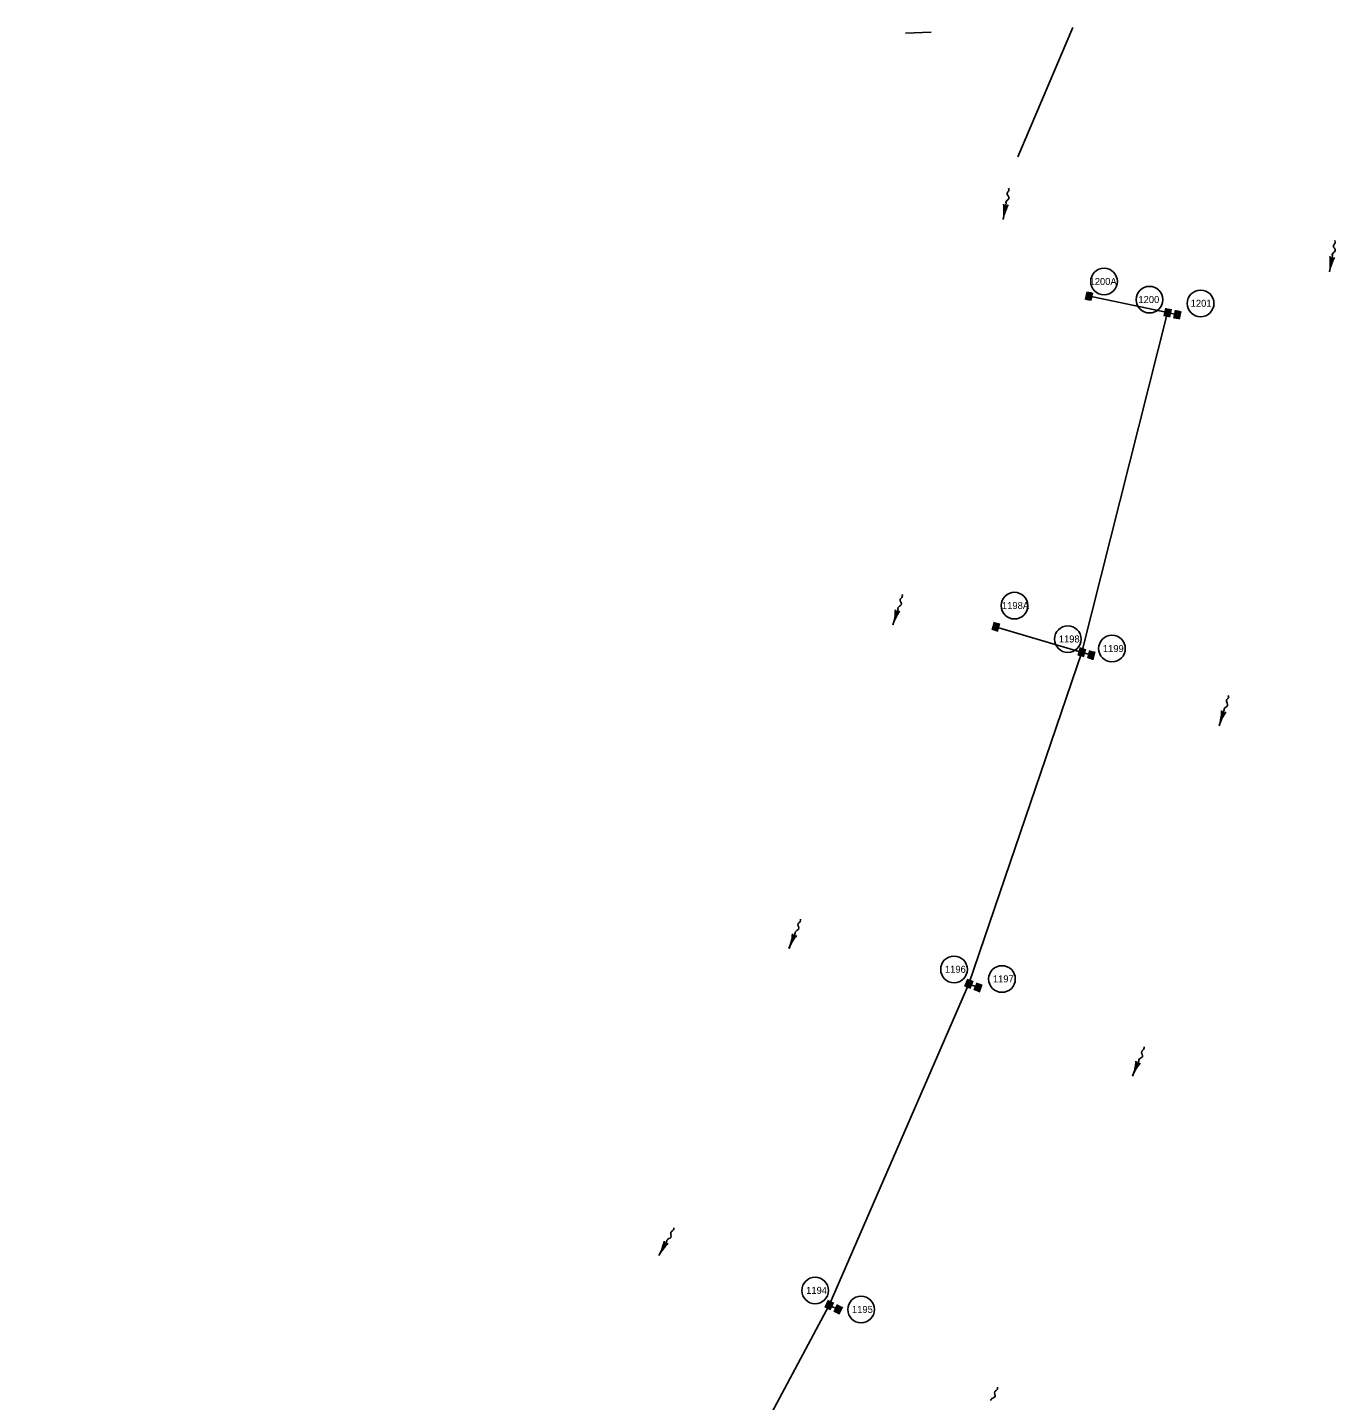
# Model space of a CAD drawing. Extents: x 594534 to 598564, y 225861 to 236229.
# Drawn here: x 597344 to 598463, y 232575 to 233750 of the extents above; entities that cross this region are included whole.
import ezdxf

# ---------------------------------------------------------------- set-up
doc = ezdxf.new("R2010")
doc.units = 0
for name, color, linetype in [('P_DRN_Flow', 7, 'Continuous'), ('P_DRN_Inlet', 7, 'Continuous'), ('P_DRN_Pipes', 7, 'Continuous'), ('P_DRN_SS_UG', 7, 'Continuous'), ('P_DRN_Text', 7, 'Continuous')]:
    doc.layers.add(name, color=color, linetype=linetype)

msp = doc.modelspace()

# ---------------------------------------------------------------- linework, layer by layer
at = {"layer": 'P_DRN_Flow'}
for p, q in [((598178.4, 233585.7), (598180.9, 233599.6)), ((598457.5, 233540.9), (598460, 233554.8)), ((598084.2, 233239), (598088.5, 233252.4)), ((598363.1, 233152.7), (598367.4, 233166.2)), ((597995.2, 232962), (598000.4, 232975.1)), ((598289.1, 232852.9), (598294.4, 232866)), ((597883.9, 232699.5), (597890.8, 232711.9))]:
    msp.add_line(p, q, dxfattribs=at)
for points in [[(598178.7, 233598.7), (598180.1, 233595.2), (598182.7, 233597.9)], [(598457.8, 233553.8), (598459.2, 233550.3), (598461.8, 233553.1)], [(598086.1, 233251.8), (598087.1, 233248.1), (598090, 233250.6)], [(598365.1, 233165.5), (598366.1, 233161.8), (598368.9, 233164.3)], [(597998.1, 232974.6), (597998.8, 232970.9), (598001.8, 232973.1)], [(598292, 232865.6), (598292.7, 232861.8), (598295.7, 232864.1)], [(597888.4, 232711.7), (597888.6, 232707.9), (597891.9, 232709.7)]]:
    msp.add_lwpolyline(points, dxfattribs=at)
for centre, start, end in [((598137.1, 233593.3), 349.6266, 7.3889), ((598219.7, 233578.2), 151.8642, 169.6266), ((598416.2, 233548.4), 349.6266, 7.3889), ((598498.8, 233533.3), 151.8642, 169.6266), ((598044.2, 233251.7), 342.3152, 0.0775), ((598124.1, 233226.2), 144.5529, 162.3152), ((598323.2, 233165.4), 342.3152, 0.0775), ((598403.1, 233139.9), 144.5529, 162.3152), ((597956.3, 232977.7), 338.0622, 355.8245), ((598034.1, 232946.3), 140.2999, 158.0622), ((598250.2, 232868.6), 338.0622, 355.8245), ((598328, 232837.3), 140.2999, 158.0622), ((597847.2, 232719.8), 331.0834, 348.8457), ((597920.7, 232679.2), 133.3211, 151.0834)]:
    msp.add_arc(centre, 42, start, end, dxfattribs=at)
for points in [[(598180.9, 233599.6), (598180.8, 233600.4), (598183.3, 233603.6), (598181.8, 233607.9), (598183.3, 233610.5), (598182.9, 233612.3)], [(598460, 233554.8), (598459.9, 233555.6), (598462.4, 233558.8), (598460.9, 233563.1), (598462.4, 233565.7), (598462.1, 233567.5)], [(598088.5, 233252.4), (598088.4, 233253.3), (598091.3, 233256.1), (598090.4, 233260.6), (598092.1, 233263), (598092.1, 233264.8)], [(598367.4, 233166.2), (598367.4, 233167), (598370.3, 233169.9), (598369.4, 233174.3), (598371.1, 233176.7), (598371, 233178.5)], [(598000.4, 232975.1), (598000.5, 232976), (598003.5, 232978.6), (598003, 232983.1), (598004.9, 232985.3), (598005, 232987.2)], [(598294.4, 232866), (598294.4, 232866.9), (598297.5, 232869.5), (598296.9, 232874), (598298.8, 232876.3), (598298.9, 232878.1)], [(597890.8, 232711.9), (597890.9, 232712.7), (597894.3, 232715), (597894.2, 232719.4), (597896.4, 232721.5), (597896.7, 232723.3)], [(598167.8, 232575.5), (598167.9, 232576.3), (598171.3, 232578.6), (598171.3, 232583.1), (598173.5, 232585.1), (598173.7, 232586.9)]]:
    msp.add_spline(points, degree=3, dxfattribs=at)
at = {"layer": 'P_DRN_Inlet'}
for p, q in [((598248.9, 233517.1), (598250.3, 233523.8)), ((598249.8, 233516.9), (598251.2, 233523.6)), ((598250.6, 233516.7), (598252.1, 233523.4)), ((598251.5, 233516.5), (598253, 233523.3)), ((598252.4, 233516.3), (598253.8, 233523.1)), ((598253.3, 233516.2), (598254.7, 233522.9)), ((598316.2, 233503), (598317.6, 233509.7)), ((598317, 233502.8), (598318.5, 233509.5)), ((598317.9, 233502.6), (598319.4, 233509.3)), ((598318.8, 233502.4), (598320.2, 233509.1)), ((598319.7, 233502.2), (598321.1, 233509)), ((598320.6, 233502), (598322, 233508.8)), ((598324.5, 233501.2), (598325.9, 233507.9)), ((598325.3, 233501), (598326.8, 233507.7)), ((598326.2, 233500.8), (598327.7, 233507.6)), ((598327.1, 233500.6), (598328.6, 233507.4)), ((598328, 233500.5), (598329.5, 233507.2)), ((598328.9, 233500.3), (598330.3, 233507)), ((598169, 233234.6), (598170.9, 233241.2)), ((598169.9, 233234.3), (598171.8, 233240.9)), ((598170.7, 233234.1), (598172.6, 233240.7)), ((598171.6, 233233.8), (598173.5, 233240.4)), ((598172.5, 233233.6), (598174.3, 233240.2)), ((598173.3, 233233.3), (598175.2, 233240)), ((598242.6, 233212.7), (598244.5, 233219.4)), ((598243.5, 233212.5), (598245.3, 233219.1)), ((598244.3, 233212.2), (598246.2, 233218.9)), ((598245.2, 233212), (598247.1, 233218.6)), ((598246.1, 233211.8), (598247.9, 233218.4)), ((598246.9, 233211.5), (598248.8, 233218.1)), ((598250.7, 233210.3), (598252.6, 233216.9)), ((598251.6, 233210.1), (598253.5, 233216.7)), ((598252.5, 233209.8), (598254.3, 233216.4)), ((598253.3, 233209.6), (598255.2, 233216.2)), ((598254.2, 233209.3), (598256.1, 233216)), ((598255.1, 233209.1), (598256.9, 233215.7)), ((598145.7, 232929.5), (598148.2, 232935.9)), ((598146.5, 232929.2), (598149, 232935.6)), ((598147.3, 232928.8), (598149.8, 232935.3)), ((598148.2, 232928.5), (598150.7, 232934.9)), ((598149, 232928.2), (598151.5, 232934.6)), ((598149.9, 232927.9), (598152.4, 232934.3)), ((598153.6, 232926.4), (598156.1, 232932.8)), ((598154.4, 232926.1), (598156.9, 232932.5)), ((598155.3, 232925.8), (598157.8, 232932.2)), ((598156.1, 232925.5), (598158.6, 232931.9)), ((598157, 232925.1), (598159.4, 232931.5)), ((598157.8, 232924.8), (598160.3, 232931.2)), ((598026.2, 232655), (598029.1, 232661.2)), ((598027, 232654.6), (598029.9, 232660.8)), ((598027.8, 232654.2), (598030.8, 232660.4)), ((598028.6, 232653.8), (598031.6, 232660)), ((598029.4, 232653.4), (598032.4, 232659.6)), ((598030.2, 232653), (598033.2, 232659.2)), ((598033.8, 232651.3), (598036.8, 232657.5)), ((598034.7, 232650.9), (598037.6, 232657.1)), ((598035.5, 232650.5), (598038.4, 232656.7)), ((598036.3, 232650.1), (598039.2, 232656.3)), ((598037.1, 232649.7), (598040, 232655.9)), ((598037.9, 232649.3), (598040.9, 232655.5))]:
    msp.add_line(p, q, dxfattribs=at)
for points in [[(598252.6, 233518.8), (598253, 233520.8), (598251, 233521.2), (598250.6, 233519.2)], [(598319.9, 233504.7), (598320.3, 233506.6), (598318.3, 233507.1), (598317.9, 233505.1)], [(598328.2, 233502.9), (598328.6, 233504.9), (598326.6, 233505.3), (598326.2, 233503.3)], [(598172.8, 233236), (598173.3, 233238), (598171.4, 233238.5), (598170.9, 233236.6)], [(598246.4, 233214.2), (598246.9, 233216.1), (598245, 233216.7), (598244.5, 233214.7)], [(598254.5, 233211.8), (598255.1, 233213.7), (598253.2, 233214.3), (598252.6, 233212.3)], [(598149.6, 232930.6), (598150.3, 232932.5), (598148.4, 232933.2), (598147.7, 232931.3)], [(598157.5, 232927.5), (598158.2, 232929.4), (598156.4, 232930.1), (598155.6, 232928.2)], [(598030.2, 232655.8), (598031, 232657.6), (598029.2, 232658.4), (598028.4, 232656.6)], [(598037.8, 232652.1), (598038.7, 232653.9), (598036.9, 232654.7), (598036, 232652.9)]]:
    msp.add_lwpolyline(points, close=True, dxfattribs=at)
at = {"layer": 'P_DRN_Pipes'}
for p, q in [((598116.8, 233745.9), (598094.8, 233745)), ((598238, 233749.8), (598191, 233639.3))]:
    msp.add_line(p, q, dxfattribs=at)
at = {"layer": 'P_DRN_SS_UG'}
for p, q in [((598249.6, 233520.5), (598319.1, 233505.9)), ((598319.1, 233505.9), (598245.7, 233215.4)), ((598319.1, 233505.9), (598327.4, 233504.1)), ((598169.9, 233237.9), (598243.1, 233216.2))]:
    msp.add_line(p, q, dxfattribs=at)
for points in [[(598245.7, 233215.4), (598149, 232931.9), (598029.7, 232657.1), (597888.5, 232392.9), (597726.4, 232141), (597544.4, 231903), (597343.9, 231680.3)], [(598245.7, 233215.4), (598253.8, 233213)], [(598149, 232931.9), (598156.9, 232928.8)], [(598029.7, 232657.1), (598037.3, 232653.4)]]:
    msp.add_lwpolyline(points, dxfattribs=at)
at = {"layer": 'P_DRN_Text'}
for centre in [(598264.7, 233532.5), (598303.6, 233517), (598347.3, 233513.8), (598188.1, 233255.3), (598233.7, 233226.7), (598271.5, 233218.6), (598136.4, 232944.2), (598177.4, 232936), (598017.6, 232669.6), (598056.9, 232653.3)]:
    msp.add_circle(centre, 11.4, dxfattribs=at)

# ---------------------------------------------------------------- texts
for s, p in [('1200A', (598252.3, 233529.6)), ('1200', (598294.1, 233514.1)), ('1201', (598338.8, 233510.9)), ('1198A', (598177.4, 233252.4)), ('1198', (598226, 233223.8)), ('1199', (598263.7, 233215.6)), ('1196', (598128.6, 232941.3)), ('1197', (598169.6, 232933.1)), ('1194', (598009.9, 232666.7)), ('1195', (598049.1, 232650.4))]:
    msp.add_text(s, height=6, dxfattribs=at).set_placement(p)

doc.saveas('drawing.dxf')
